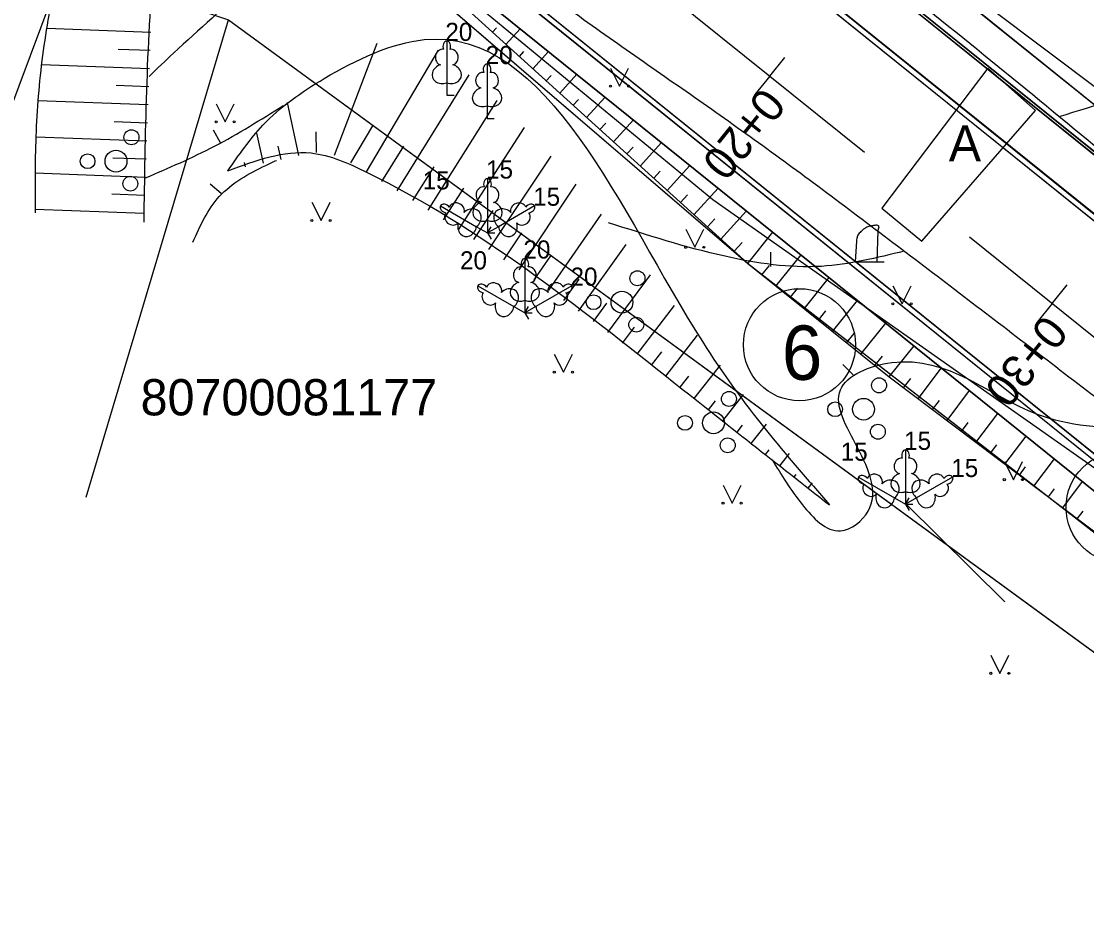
# Model space of a CAD drawing. Extents: x 514086 to 514457, y 297399 to 297567.
# Drawn here: x 514133.42 to 514162.8, y 297461.26 to 297486.33 of the extents above; entities that cross this region are included whole.
import ezdxf

# ---------------------------------------------------------------- set-up
doc = ezdxf.new("R2010")
doc.units = 0
for name, color, linetype in [('AA_Apzimejumi', 7, 'Continuous'), ('AA_Brauktuve', 7, 'Continuous'), ('AA_cela_mala', 7, 'Continuous'), ('AA_Ielas_ass', 7, 'Continuous'), ('AA_Ietve', 7, 'Continuous'), ('AA_nogaze', 7, 'Continuous'), ('AA_Nomale', 7, 'Continuous'), ('AA_Zale', 7, 'Continuous'), ('Level 1', 7, 'Continuous'), ('Level 23', 7, 'Continuous'), ('Level 29', 7, 'Continuous'), ('Level 31', 7, 'Continuous'), ('Level 32', 7, 'Continuous'), ('Level 36', 7, 'Continuous'), ('Level 37', 7, 'Continuous'), ('Level 41', 7, 'Continuous'), ('Level 45', 7, 'Continuous'), ('Level 46', 7, 'Continuous'), ('Level 59', 7, 'Continuous'), ('Level 8', 7, 'Continuous')]:
    doc.layers.add(name, color=color, linetype=linetype)

msp = doc.modelspace()

# ---------------------------------------------------------------- linework, layer by layer
at = {"layer": 'AA_Apzimejumi'}
for centre in [(514154.882, 297477.406), (514163.781, 297472.919)]:
    msp.add_circle(centre, 1.546, dxfattribs=at)
at = {"layer": 'AA_Brauktuve'}
for points in [[(514184.371, 297463.607), (514146.894, 297493.805)], [(514139.852, 297493.058), (514181.234, 297459.714)]]:
    msp.add_lwpolyline(points, dxfattribs=at)
at = {"layer": 'AA_cela_mala'}
for p, q in [((514147.835, 297494.973), (514185.313, 297464.775)), ((514185.262, 297464.713), (514147.785, 297494.911)), ((514146.894, 297493.805), (514184.371, 297463.607)), ((514184.466, 297463.724), (514146.988, 297493.922)), ((514139.758, 297492.942), (514181.14, 297459.597)), ((514139.852, 297493.058), (514181.234, 297459.714))]:
    msp.add_line(p, q, dxfattribs=at)
at = {"layer": 'AA_Ielas_ass'}
for p, q in [((514129.973, 297475.496), (514137.676, 297496.077)), ((514145.326, 297491.858), (514156.673, 297482.715)), ((514154.063, 297484.818), (514154.476, 297485.33)), ((514154.063, 297484.818), (514153.65, 297484.306)), ((514159.568, 297480.383), (514182.803, 297461.661)), ((514161.85, 297478.544), (514162.263, 297479.056)), ((514161.85, 297478.544), (514161.437, 297478.032))]:
    msp.add_line(p, q, dxfattribs=at)
at = {"layer": 'AA_Ietve'}
for points in [[(514185.262, 297464.713), (514147.791, 297494.906)], [(514146.982, 297493.927), (514184.466, 297463.724)]]:
    msp.add_lwpolyline(points, dxfattribs=at)
at = {"layer": 'AA_nogaze'}
for p, q in [((514146.418, 297486.029), (514146.53, 297486.152)), ((514146.788, 297485.693), (514147.181, 297486.126)), ((514147.159, 297485.357), (514147.282, 297485.493)), ((514147.529, 297485.021), (514147.961, 297485.497)), ((514147.899, 297484.685), (514148.035, 297484.834)), ((514148.27, 297484.349), (514148.741, 297484.869)), ((514148.64, 297484.013), (514148.787, 297484.176)), ((514149.01, 297483.677), (514149.521, 297484.24)), ((514149.381, 297483.341), (514149.54, 297483.517)), ((514149.751, 297483.006), (514150.301, 297483.612)), ((514150.492, 297482.334), (514151.081, 297482.983)), ((514150.122, 297482.67), (514150.292, 297482.858)), ((514151.233, 297481.662), (514151.861, 297482.355)), ((514150.862, 297481.998), (514151.045, 297482.199)), ((514151.973, 297480.99), (514152.641, 297481.726)), ((514151.603, 297481.326), (514151.797, 297481.54)), ((514152.344, 297480.654), (514152.55, 297480.882)), ((514152.714, 297480.318), (514153.421, 297481.098)), ((514153.455, 297479.647), (514154.149, 297480.511)), ((514153.085, 297479.983), (514153.302, 297480.223)), ((514154.235, 297479.021), (514154.928, 297479.884)), ((514153.845, 297479.334), (514154.053, 297479.593)), ((514155.015, 297478.395), (514155.706, 297479.256)), ((514154.625, 297478.708), (514154.833, 297478.967)), ((514155.795, 297477.769), (514156.485, 297478.629)), ((514155.405, 297478.082), (514155.612, 297478.34)), ((514156.574, 297477.143), (514157.264, 297478.001)), ((514156.184, 297477.456), (514156.391, 297477.714)), ((514157.354, 297476.517), (514158.042, 297477.374)), ((514156.964, 297476.83), (514157.171, 297477.087)), ((514158.152, 297475.915), (514158.795, 297476.767)), ((514157.753, 297476.216), (514157.949, 297476.475)), ((514158.951, 297475.313), (514159.574, 297476.139)), ((514158.552, 297475.614), (514158.742, 297475.865)), ((514159.35, 297475.012), (514159.534, 297475.256)), ((514159.749, 297474.711), (514160.353, 297475.512)), ((514160.548, 297474.108), (514161.133, 297474.884)), ((514160.149, 297474.409), (514160.327, 297474.646)), ((514161.346, 297473.506), (514161.912, 297474.256)), ((514160.947, 297473.807), (514161.12, 297474.036)), ((514162.145, 297472.904), (514162.691, 297473.628)), ((514161.746, 297473.205), (514161.912, 297473.426)), ((514162.544, 297472.603), (514162.705, 297472.817))]:
    msp.add_line(p, q, dxfattribs=at)
msp.add_lwpolyline([(514139.381, 297492.411), (514153.448, 297479.653), (514157.356, 297476.515), (514190.113, 297451.817)], dxfattribs=at)
at = {"layer": 'AA_Nomale'}
for points in [[(514181.14, 297459.597), (514139.77, 297492.933)], [(514139.413, 297492.389), (514139.411, 297492.386), (514180.732, 297459.091)]]:
    msp.add_lwpolyline(points, dxfattribs=at)
at = {"layer": 'AA_Zale'}
for p, q in [((514146.591, 297497.26), (514175.859, 297473.677)), ((514139.35, 297492.435), (514180.732, 297459.091))]:
    msp.add_line(p, q, dxfattribs=at)
for points in [[(514197.26, 297461.293), (514196.873, 297461.611), (514193.845, 297459.804), (514175.859, 297473.677), (514146.591, 297497.26)], [(514147.835, 297494.973), (514185.313, 297464.775)], [(514180.732, 297459.091), (514139.411, 297492.386), (514139.381, 297492.411)], [(514139.036, 297492.046), (514153.448, 297479.653), (514180.419, 297458.702)], [(514139.139, 297491.971), (514139.135, 297491.966), (514153.455, 297479.647), (514180.419, 297458.702)]]:
    msp.add_lwpolyline(points, dxfattribs=at)
at = {"layer": 'Level 1'}
for p, q in [((514145.156, 297484.635), (514145.156, 297484.288)), ((514145.156, 297484.288), (514145.356, 297484.288)), ((514146.267, 297483.997), (514146.267, 297483.65)), ((514146.267, 297483.65), (514146.467, 297483.65)), ((514146.279, 297480.837), (514146.279, 297480.49)), ((514145.978, 297480.663), (514146.279, 297480.49)), ((514146.279, 297480.49), (514146.379, 297480.663)), ((514146.58, 297480.663), (514146.279, 297480.49)), ((514146.279, 297480.49), (514146.479, 297480.49)), ((514146.279, 297480.49), (514146.379, 297480.317)), ((514147.309, 297478.631), (514147.309, 297478.284)), ((514147.008, 297478.457), (514147.309, 297478.284)), ((514147.309, 297478.284), (514147.409, 297478.457)), ((514147.61, 297478.457), (514147.309, 297478.284)), ((514147.309, 297478.284), (514147.509, 297478.284)), ((514147.309, 297478.284), (514147.409, 297478.111)), ((514157.808, 297473.352), (514157.808, 297473.005)), ((514157.507, 297473.178), (514157.808, 297473.005)), ((514160.542, 297470.313), (514157.804, 297473.025)), ((514157.808, 297473.005), (514157.908, 297473.178)), ((514158.109, 297473.178), (514157.808, 297473.005)), ((514157.808, 297473.005), (514158.008, 297473.005)), ((514157.808, 297473.005), (514157.908, 297472.832))]:
    msp.add_line(p, q, dxfattribs=at)
for points in [[(514145.156, 297485.788), (514145.156, 297484.635)], [(514145.246, 297485.556), (514145.245, 297485.557)], [(514146.267, 297485.15), (514146.267, 297483.997)], [(514146.357, 297484.918), (514146.356, 297484.919)], [(514146.279, 297481.99), (514146.279, 297480.837)], [(514146.369, 297481.758), (514146.368, 297481.759)], [(514144.98, 297481.24), (514145.978, 297480.663)], [(514145.226, 297481.201), (514145.225, 297481.201)], [(514147.578, 297481.24), (514146.58, 297480.663)], [(514147.422, 297481.046), (514147.422, 297481.048)], [(514147.309, 297479.784), (514147.309, 297478.631)], [(514147.399, 297479.552), (514147.398, 297479.553)], [(514146.01, 297479.034), (514147.008, 297478.457)], [(514146.256, 297478.995), (514146.255, 297478.995)], [(514148.608, 297479.034), (514147.61, 297478.457)], [(514148.452, 297478.84), (514148.452, 297478.842)], [(514157.808, 297474.505), (514157.808, 297473.352)], [(514157.898, 297474.273), (514157.897, 297474.274)], [(514156.509, 297473.755), (514157.507, 297473.178)], [(514156.755, 297473.716), (514156.754, 297473.716)], [(514159.107, 297473.755), (514158.109, 297473.178)], [(514158.951, 297473.561), (514158.951, 297473.563)]]:
    msp.add_lwpolyline(points, dxfattribs=at)
for centre, radius in [((514136.461, 297483.129), 0.207), ((514135.25, 297482.469), 0.204), ((514136.034, 297482.469), 0.301), ((514136.429, 297481.849), 0.205), ((514150.414, 297479.239), 0.207), ((514149.203, 297478.579), 0.204), ((514149.987, 297478.579), 0.301), ((514150.382, 297477.959), 0.205), ((514157.077, 297476.285), 0.207), ((514152.937, 297475.909), 0.207), ((514156.65, 297475.625), 0.301), ((514152.51, 297475.249), 0.301), ((514155.866, 297475.625), 0.204), ((514151.726, 297475.249), 0.204), ((514157.045, 297475.005), 0.205), ((514152.905, 297474.629), 0.205)]:
    msp.add_circle(centre, radius, dxfattribs=at)
for centre, major_axis, ratio, start_param, end_param in [((514145.028, 297485.343), (-0.039, -0.212), 0.861323, 3.141593, 6.283185), ((514145.156, 297485.638), (0, -0.15), 0.707107, 3.14537, 5.287485), ((514145.156, 297485.638), (0, -0.15), 0.707107, 0.995701, 3.137816), ((514145.284, 297485.343), (0.039, -0.212), 0.861323, 0, 3.141593), ((514145.066, 297484.881), (0.307, 0.095), 0.814445, 1.570796, 4.752015), ((514145.246, 297484.881), (-0.307, 0.095), 0.814445, 1.531171, 4.712389), ((514146.267, 297485), (0, -0.15), 0.707107, 3.14537, 5.287485), ((514146.267, 297485), (0, -0.15), 0.707107, 0.995701, 3.137816), ((514146.139, 297484.705), (-0.039, -0.212), 0.861323, 3.141593, 6.283185), ((514146.395, 297484.705), (0.039, -0.212), 0.861323, 0, 3.141593), ((514146.177, 297484.243), (0.307, 0.095), 0.814445, 1.570796, 4.752015), ((514146.357, 297484.243), (-0.307, 0.095), 0.814445, 1.531171, 4.712389), ((514146.151, 297481.545), (-0.039, -0.212), 0.861323, 3.141593, 6.283185), ((514146.279, 297481.84), (0, -0.15), 0.707107, 3.14537, 5.287485), ((514146.279, 297481.84), (0, -0.15), 0.707107, 0.995701, 3.137816), ((514146.407, 297481.545), (0.039, -0.212), 0.861323, 0, 3.141593), ((514145.11, 297481.165), (0.13, -0.075), 0.707107, 3.14537, 5.287485), ((514145.11, 297481.165), (0.13, -0.075), 0.707107, 0.995701, 3.137816), ((514145.429, 297481.129), (0.203, -0.073), 0.861323, 0, 3.141593), ((514145.81, 297480.864), (-0.236, -0.218), 0.814445, 1.531171, 4.712389), ((514146.189, 297481.083), (0.307, 0.095), 0.814445, 1.570796, 4.752015), ((514146.369, 297481.083), (-0.307, 0.095), 0.814445, 1.531171, 4.712389), ((514146.748, 297480.864), (0.236, -0.218), 0.814445, 1.570796, 4.752015), ((514147.129, 297481.129), (-0.203, -0.073), 0.861323, 3.141593, 6.283185), ((514147.448, 297481.165), (-0.13, -0.075), 0.707107, 3.14537, 5.287485), ((514147.448, 297481.165), (-0.13, -0.075), 0.707107, 0.995701, 3.137816), ((514145.301, 297480.906), (0.165, -0.14), 0.861323, 3.141593, 6.283185), ((514147.257, 297480.906), (-0.165, -0.14), 0.861323, 0, 3.141593), ((514145.721, 297480.709), (0.071, 0.313), 0.814445, 1.570796, 4.752015), ((514146.837, 297480.709), (-0.071, 0.313), 0.814445, 1.531171, 4.712389), ((514147.309, 297479.634), (0, -0.15), 0.707107, 3.14537, 5.287485), ((514147.309, 297479.634), (0, -0.15), 0.707107, 0.995701, 3.137816), ((514147.181, 297479.339), (-0.039, -0.212), 0.861323, 3.141593, 6.283185), ((514147.437, 297479.339), (0.039, -0.212), 0.861323, 0, 3.141593), ((514146.14, 297478.959), (0.13, -0.075), 0.707107, 0.995701, 3.137816), ((514146.459, 297478.923), (0.203, -0.073), 0.861323, 0, 3.141593), ((514147.219, 297478.877), (0.307, 0.095), 0.814445, 1.570796, 4.752015), ((514147.399, 297478.877), (-0.307, 0.095), 0.814445, 1.531171, 4.712389), ((514148.159, 297478.923), (-0.203, -0.073), 0.861323, 3.141593, 6.283185), ((514148.478, 297478.959), (-0.13, -0.075), 0.707107, 3.14537, 5.287485), ((514146.14, 297478.959), (0.13, -0.075), 0.707107, 3.14537, 5.287485), ((514146.331, 297478.7), (0.165, -0.14), 0.861323, 3.141593, 6.283185), ((514146.84, 297478.658), (-0.236, -0.218), 0.814445, 1.531171, 4.712389), ((514147.778, 297478.658), (0.236, -0.218), 0.814445, 1.570796, 4.752015), ((514148.287, 297478.7), (-0.165, -0.14), 0.861323, 0, 3.141593), ((514148.478, 297478.959), (-0.13, -0.075), 0.707107, 0.995701, 3.137816), ((514146.751, 297478.503), (0.071, 0.313), 0.814445, 1.570796, 4.752015), ((514147.867, 297478.503), (-0.071, 0.313), 0.814445, 1.531171, 4.712389), ((514157.808, 297474.355), (0, -0.15), 0.707107, 3.14537, 5.287485), ((514157.808, 297474.355), (0, -0.15), 0.707107, 0.995701, 3.137816), ((514157.68, 297474.06), (-0.039, -0.212), 0.861323, 3.141593, 6.283185), ((514157.936, 297474.06), (0.039, -0.212), 0.861323, 0, 3.141593), ((514156.639, 297473.68), (0.13, -0.075), 0.707107, 0.995701, 3.137816), ((514156.958, 297473.644), (0.203, -0.073), 0.861323, 0, 3.141593), ((514157.718, 297473.598), (0.307, 0.095), 0.814445, 1.570796, 4.752015), ((514157.898, 297473.598), (-0.307, 0.095), 0.814445, 1.531171, 4.712389), ((514158.658, 297473.644), (-0.203, -0.073), 0.861323, 3.141593, 6.283185), ((514158.977, 297473.68), (-0.13, -0.075), 0.707107, 3.14537, 5.287485), ((514156.639, 297473.68), (0.13, -0.075), 0.707107, 3.14537, 5.287485), ((514156.83, 297473.421), (0.165, -0.14), 0.861323, 3.141593, 6.283185), ((514157.339, 297473.379), (-0.236, -0.218), 0.814445, 1.531171, 4.712389), ((514158.277, 297473.379), (0.236, -0.218), 0.814445, 1.570796, 4.752015), ((514158.786, 297473.421), (-0.165, -0.14), 0.861323, 0, 3.141593), ((514158.977, 297473.68), (-0.13, -0.075), 0.707107, 0.995701, 3.137816), ((514157.25, 297473.224), (0.071, 0.313), 0.814445, 1.570796, 4.752015), ((514158.366, 297473.224), (-0.071, 0.313), 0.814445, 1.531171, 4.712389)]:
    msp.add_ellipse(centre, major_axis=major_axis, ratio=ratio, start_param=start_param, end_param=end_param, dxfattribs=at)
at = {"layer": 'Level 23'}
for p, q in [((514149.671, 297485.038), (514149.921, 297484.538)), ((514149.921, 297484.538), (514150.171, 297485.038)), ((514138.794, 297484.053), (514139.044, 297483.553)), ((514139.044, 297483.553), (514139.294, 297484.053)), ((514141.438, 297481.337), (514141.688, 297480.837)), ((514141.688, 297480.837), (514141.938, 297481.337)), ((514151.745, 297480.595), (514151.995, 297480.095)), ((514151.995, 297480.095), (514152.245, 297480.595)), ((514157.461, 297479.032), (514157.711, 297478.532)), ((514157.711, 297478.532), (514157.961, 297479.032)), ((514148.122, 297477.149), (514148.372, 297476.649)), ((514148.372, 297476.649), (514148.622, 297477.149)), ((514160.533, 297474.182), (514160.783, 297473.682)), ((514160.783, 297473.682), (514161.033, 297474.182)), ((514152.775, 297473.532), (514153.025, 297473.032)), ((514153.025, 297473.032), (514153.275, 297473.532)), ((514160.158, 297468.838), (514160.408, 297468.338)), ((514160.408, 297468.338), (514160.658, 297468.838))]:
    msp.add_line(p, q, dxfattribs=at)
for centre, radius in [((514149.671, 297484.537), 0.028), ((514150.171, 297484.537), 0.0263), ((514138.794, 297483.553), 0.028), ((514139.294, 297483.553), 0.0263), ((514141.437, 297480.836), 0.028), ((514141.937, 297480.836), 0.0263), ((514151.745, 297480.094), 0.028), ((514152.245, 297480.094), 0.0263), ((514157.46, 297478.532), 0.028), ((514157.96, 297478.532), 0.0263), ((514148.121, 297476.649), 0.028), ((514148.621, 297476.649), 0.0263), ((514160.532, 297473.682), 0.028), ((514161.032, 297473.682), 0.0263), ((514152.775, 297473.031), 0.028), ((514153.275, 297473.031), 0.0263), ((514160.157, 297468.338), 0.028), ((514160.657, 297468.338), 0.0263)]:
    msp.add_circle(centre, radius, dxfattribs=at)
at = {"layer": 'Level 29'}
for p, q in [((514139.316, 297503.122), (514175.859, 297473.677)), ((514135.213, 297473.203), (514139.134, 297486.37)), ((514139.134, 297486.37), (514229.261, 297420.493))]:
    msp.add_line(p, q, dxfattribs=at)
at = {"layer": 'Level 31'}
for p, q in [((514136.996, 297486.02), (514134.124, 297486.128)), ((514136.977, 297485.52), (514136.098, 297485.553)), ((514142.057, 297482.636), (514143.236, 297485.722)), ((514142.941, 297482.173), (514144.924, 297485.534)), ((514136.958, 297485.02), (514133.983, 297485.133)), ((514143.792, 297481.648), (514145.769, 297484.849)), ((514136.939, 297484.521), (514136.035, 297484.555)), ((514136.92, 297484.021), (514133.879, 297484.136)), ((514141.076, 297482.624), (514140.764, 297484.089)), ((514144.639, 297481.117), (514146.55, 297484.142)), ((514136.901, 297483.521), (514135.984, 297483.556)), ((514140.098, 297482.415), (514139.921, 297483.247)), ((514141.567, 297482.713), (514141.557, 297483.278)), ((514142.51, 297482.427), (514143.113, 297483.449)), ((514145.482, 297480.578), (514147.301, 297483.396)), ((514136.882, 297483.022), (514133.819, 297483.137)), ((514143.367, 297481.91), (514143.971, 297482.889)), ((514140.587, 297482.52), (514140.51, 297482.883)), ((514146.318, 297480.03), (514148.038, 297482.611)), ((514136.864, 297482.522), (514135.947, 297482.557)), ((514139.609, 297482.311), (514139.582, 297482.436)), ((514144.217, 297481.384), (514144.805, 297482.315)), ((514136.845, 297482.022), (514133.806, 297482.137)), ((514139.12, 297482.207), (514139.118, 297482.217)), ((514145.062, 297480.85), (514145.626, 297481.723)), ((514147.15, 297479.475), (514148.724, 297481.837)), ((514136.826, 297481.523), (514135.92, 297481.557)), ((514136.807, 297481.023), (514133.806, 297481.137)), ((514145.902, 297480.307), (514146.438, 297481.111)), ((514147.974, 297478.909), (514149.424, 297481.004)), ((514146.734, 297479.752), (514147.229, 297480.495)), ((514148.792, 297478.333), (514150.104, 297480.172)), ((514147.563, 297479.193), (514148.022, 297479.856)), ((514148.385, 297478.624), (514148.803, 297479.21)), ((514149.601, 297477.745), (514150.771, 297479.33)), ((514149.198, 297478.042), (514149.574, 297478.551)), ((514150.403, 297477.148), (514151.433, 297478.485)), ((514150.003, 297477.448), (514150.329, 297477.89)), ((514151.195, 297476.538), (514152.067, 297477.669)), ((514150.799, 297476.843), (514151.084, 297477.213)), ((514151.983, 297475.922), (514152.709, 297476.844)), ((514151.59, 297476.231), (514151.831, 297476.537)), ((514152.376, 297475.612), (514152.57, 297475.86)), ((514152.768, 297475.303), (514153.341, 297476.031)), ((514153.161, 297474.994), (514153.31, 297475.183)), ((514153.554, 297474.684), (514153.974, 297475.218)), ((514153.947, 297474.375), (514154.05, 297474.506)), ((514154.34, 297474.066), (514154.607, 297474.405)), ((514154.733, 297473.756), (514154.79, 297473.829)), ((514155.125, 297473.447), (514155.239, 297473.592)), ((514155.518, 297473.138), (514155.53, 297473.152))]:
    msp.add_line(p, q, dxfattribs=at)
for points in [[(514136.518, 297490.897), (514137.074, 297489.513), (514137.074, 297488.075), (514136.798, 297480.788)], [(514139.12, 297482.207), (514140.085, 297483.46), (514141.778, 297484.753), (514144.532, 297485.825), (514152.206, 297477.49), (514155.71, 297472.987)], [(514139.12, 297482.207), (514141.414, 297482.696), (514142.959, 297482.162), (514151.422, 297476.363), (514155.71, 297472.987)]]:
    msp.add_spline(points, degree=3, dxfattribs=at)
at = {"layer": 'Level 32'}
for p, q in [((514138.92, 297482.975), (514138.726, 297483.325)), ((514138.938, 297481.58), (514138.634, 297481.839)), ((514154.093, 297479.562), (514154.089, 297479.961)), ((514156.359, 297476.572), (514156.079, 297476.858))]:
    msp.add_line(p, q, dxfattribs=at)
for points in [[(514137.103, 297493.136), (514138.988, 297492.009), (514140.65, 297490.75), (514139.702, 297487.535), (514137.621, 297485.453), (514136.95, 297484.807)], [(514162.045, 297483.701), (514168.12, 297485.367), (514175.973, 297486.222)], [(514136.844, 297482.007), (514138.754, 297482.886), (514140.648, 297484.007)], [(514138.156, 297480.238), (514138.882, 297481.494), (514140.163, 297482.353), (514140.461, 297482.493)], [(514157.774, 297479.989), (514155.487, 297479.568), (514152.829, 297479.846), (514149.619, 297480.772)], [(514154.132, 297474.229), (514154.967, 297472.986), (514156.01, 297472.272), (514156.777, 297472.814), (514156.486, 297474.559), (514156.01, 297476.158), (514157.426, 297476.912), (514161.437, 297475.49), (514164.213, 297475.068)]]:
    msp.add_spline(points, degree=3, dxfattribs=at)
at = {"layer": 'Level 36'}
msp.add_spline([(514135.944, 297494.184), (514135.826, 297493.769), (514135.201, 297491.331), (514134.701, 297489.124), (514134.467, 297488.021), (514134.358, 297487.468), (514134.253, 297486.913), (514133.928, 297484.691), (514133.806, 297482.455), (514133.806, 297481.042)], degree=3, dxfattribs=at)
at = {"layer": 'Level 37'}
msp.add_lwpolyline([(514160.08, 297485.041), (514157.151, 297481.174), (514158.258, 297480.262), (514161.395, 297483.865), (514160.08, 297485.041)], dxfattribs=at)
for points in [[(514139.874, 297497.035), (514148.452, 297493.087), (514152.9, 297490.654), (514155.012, 297489.24), (514157.055, 297487.727), (514160.163, 297485.252), (514163.225, 297482.729), (514166.288, 297480.21), (514169.399, 297477.75), (514184.679, 297466.049), (514188.685, 297462.979), (514190.692, 297461.445), (514192.708, 297459.912), (514193.134, 297459.688), (514193.613, 297459.574), (514194.114, 297459.524), (514194.606, 297459.489), (514195.045, 297459.442), (514195.506, 297459.417), (514195.979, 297459.548), (514196.259, 297459.707)], [(514136.849, 297494.086), (514140.775, 297492.444), (514142.699, 297491.153), (514143.967, 297490.173), (514145.225, 297489.179), (514146.485, 297488.19), (514147.764, 297487.226), (514149.635, 297485.885), (514151.52, 297484.563), (514153.402, 297483.236), (514155.263, 297481.88), (514159.161, 297478.934), (514163.043, 297475.965), (514166.923, 297472.996), (514170.82, 297470.048), (514173.26, 297468.237), (514175.709, 297466.438), (514178.159, 297464.639), (514180.6, 297462.828), (514184.429, 297459.874), (514186.323, 297458.371), (514188.215, 297456.863), (514189.034, 297456.154), (514191.11, 297453.709)]]:
    msp.add_spline(points, degree=3, dxfattribs=at)
at = {"layer": 'Level 41'}
for p, q in [((514157.021, 297479.693), (514157.055, 297480.558)), ((514156.452, 297480.266), (514156.421, 297479.693)), ((514156.421, 297479.693), (514156.721, 297479.693)), ((514156.721, 297479.693), (514157.021, 297479.693)), ((514157.021, 297479.693), (514157.221, 297479.693))]:
    msp.add_line(p, q, dxfattribs=at)
msp.add_spline([(514157.055, 297480.558), (514157.059, 297480.589), (514157.062, 297480.6), (514157.077, 297480.662), (514157.047, 297480.697), (514156.925, 297480.691), (514156.821, 297480.673), (514156.715, 297480.634), (514156.65, 297480.59), (514156.575, 297480.526), (514156.495, 297480.428), (514156.464, 297480.339), (514156.452, 297480.265)], degree=3, dxfattribs=at)
at = {"layer": 'Level 45'}
msp.add_lwpolyline([(514142.645, 297489.455), (514144.367, 297488.114), (514148.432, 297484.764), (514152.497, 297481.414), (514158.438, 297477.231), (514164.38, 297473.048), (514165.491, 297472.425)], dxfattribs=at)
at = {"layer": 'Level 46'}
msp.add_lwpolyline([(514139.134, 297486.37), (514229.261, 297420.493), (514237.863, 297414.208), (514250.009, 297428.181), (514295.433, 297494.723), (514312.775, 297524.542), (514316.491, 297528.738), (514320.446, 297531.016), (514328.236, 297532.215), (514332.539, 297530.572), (514332.631, 297530.536), (514341.642, 297542.18), (514320.211, 297553.997), (514285.885, 297496.27), (514243.195, 297433.696), (514241.534, 297432.407), (514239.451, 297432.203), (514209.969, 297445.237), (514194.45, 297457.413), (514175.859, 297473.677), (514139.316, 297503.122), (514133.046, 297508.174), (514130.604, 297489.221)], close=True, dxfattribs=at)
at = {"layer": 'Level 8'}
msp.add_lwpolyline([(514200.623, 297456.189), (514178.139, 297473.151), (514155.647, 297490.079), (514143.111, 297496.557), (514135.656, 297500), (514119.377, 297505.512), (514108.036, 297513.213), (514096.037, 297522.278)], dxfattribs=at)

# ---------------------------------------------------------------- texts
at = {"layer": 'AA_Apzimejumi'}
msp.add_text('6', height=1.5, dxfattribs=at).set_placement((514154.396, 297476.437))
at = {"layer": 'AA_Ielas_ass'}
for s, p in [(' 0+20', (514154.063, 297484.818)), (' 0+30', (514161.85, 297478.544))]:
    msp.add_text(s, height=0.9, rotation=231.1394, dxfattribs=at).set_placement(p)
at = {"layer": 'Level 1'}
for s, p in [(' 20', (514144.931, 297485.788)), (' 20', (514146.042, 297485.15)), (' 15', (514146.054, 297481.99)), (' 15', (514144.305, 297481.69)), (' 15', (514147.353, 297481.24)), (' 20', (514147.084, 297479.784)), (' 20', (514145.335, 297479.484)), (' 20', (514148.383, 297479.034)), (' 15', (514157.583, 297474.505)), (' 15', (514155.834, 297474.205)), (' 15', (514158.882, 297473.755))]:
    msp.add_text(s, height=0.5, dxfattribs=at).set_placement(p)
at = {"layer": 'Level 37'}
msp.add_text('A', height=1, dxfattribs=at).set_placement((514159, 297482.462))
at = {"layer": 'Level 59'}
msp.add_text('80700081177', height=1, dxfattribs=at).set_placement((514136.712, 297475.456))

doc.saveas('drawing.dxf')
